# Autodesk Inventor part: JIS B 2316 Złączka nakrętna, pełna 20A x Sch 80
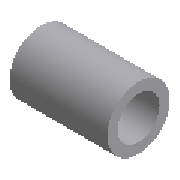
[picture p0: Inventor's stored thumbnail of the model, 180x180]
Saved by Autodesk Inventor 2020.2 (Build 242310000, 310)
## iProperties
Manager: www.cadconsulting.pl
Company: Fabian Stasiak CAD Consulting
IsCustomPart: 0
NAME: PIPING: JIS B 2316 Full Coupling
DATA: <meta><inlinegroups number="1" deflen="2.56"></inlinegroups><connections number="2"></connections><angles><a>3.14159265358979</a></angles></meta>
Created: 2014-02
Part Number: JIS B 2316 Złączka nakrętna, pełna 20A x Sch 80
Material: Stal
Description: Złączka nakrętna
Document SubType Name: Modeling
Standard: JIS B 2316
Designer: F.Stasiak
Standards Organization: JIS
Language: pl-PL
Size Designation: 20A x Sch 80
Categories: <MemberInstance><Categories><Category DisplayName="Rury cienko- i grubościenne" InternalName="4347fa0f-2144-441d-94cd-e3e15c92b736" Mnemonic="TUBEANDPIPE"><Cate
Density: 1 g/cm^3
Appearance: Płyta
Catalog Web Link: www.expertbooks.pl
Author: F.Stasiak
Subject: Zbiór ćwiczeń. Autodesk Inventor 2020. Kurs Professional
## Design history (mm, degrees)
sketch "Sketch1"
  geometry: L1 (0, 0)-(34.9, 0); L2 (34.9, 0)-(34.9, 13.6); L3 (34.9, 13.6)-(34.9, 17.9); L4 (34.9, 17.9)-(0, 17.9); L5 (17.45, 0)-(17.45, 17.9); L6 (34.9, 13.6)-(22.2, 13.6); L7 (22.2, 13.6)-(22.2, 10.7); L8 (22.2, 10.7)-(12.7, 10.7); L9 (0, 13.6)-(0, 17.9); L10 (0, 13.6)-(12.7, 13.6); L11 (12.7, 13.6)-(12.7, 10.7); L12 (0, 0)-(0, 13.6); L13 (12.7, 10.7)-(12.7, 0); L14 (22.2, 10.7)-(22.2, 0); 1 further point
  constraints: 28 end point, 4 perpendicular, 4 symmetric about line, 2 horizontal, 2 midpoint, 2 parallel, 2 point on line, 1 coincident, 1 collinear, 4 other
  dimensions: "d0" = 27.2 diameter of L2.end L1 (= S); "d1" = 21.4 diameter of L8 L1 (= D); "d2" = 35.8 diameter of L4 L1 (= S + 2 x T); "d4" = 9.5 distance of L7.end L8.end (= E1); "d5" = 12.7 distance of L9.start L10.end (= C1)
revolve "Revolution1" sketch "Sketch1" stored, may be unused: angle "d10" = 90 deg
workpoint "Work Point1"
workpoint "Work Point2"
workaxis "Work Axis1"
workpoint "Work Point3"
workaxis "Work Axis2"
workpoint "Work Point4"
body "Solid1"
other parameters: "S" = 27.2 [user parameter; used in 2 equation terms], "E1" = 9.5 [user parameter; used in 1 equation term], "D" = 21.4 [user parameter; used in 1 equation term], "C1" = 12.7 [user parameter; used in 1 equation term], "T" = 4.3 [user parameter; used in 1 equation term], "Size_Designation" = 12.345 [user parameter]
